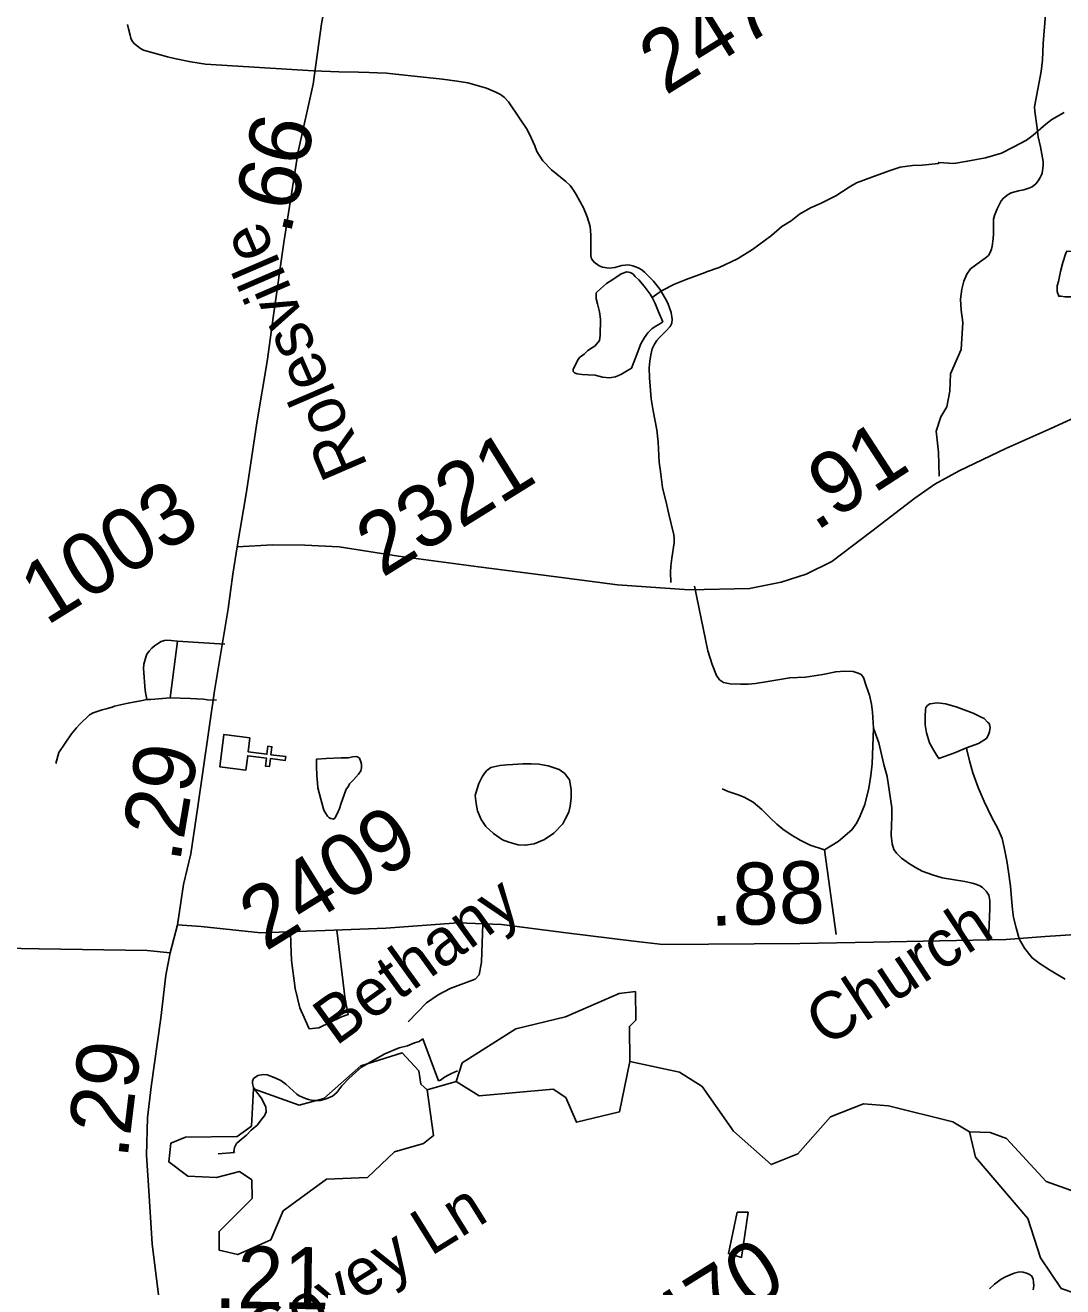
# Model space of a CAD drawing. Extents: x 2001466 to 31450019, y -30647475 to 847247.
# Drawn here: x 2163317 to 2167496, y 761240 to 766322 of the extents above; entities that cross this region are included whole.
import ezdxf

# ---------------------------------------------------------------- set-up
doc = ezdxf.new("R2010")
doc.units = 0
for name, color, linetype in [('Exist Cultural Church CELL', 7, 'Continuous'), ('Exist Hydrographic Misc Water Feature', 7, 'Continuous'), ('Exist Road Non-System Type 51', 7, 'Continuous'), ('Exist Road Secondary Mileage Hundredths English Label', 7, 'Continuous'), ('Exist Road Secondary Type 51 Attributed', 7, 'Continuous'), ('Exist Road Secondary Type 51 Label', 7, 'Continuous'), ('Exist Road Secondary Type 51 Number Label', 7, 'Continuous')]:
    doc.layers.add(name, color=color, linetype=linetype)

msp = doc.modelspace()

# ---------------------------------------------------------------- linework, layer by layer
at = {"layer": 'Exist Cultural Church CELL'}
msp.add_lwpolyline([(2164222.4, 763451.5), (2164215.5, 763395), (2164291, 763385.6), (2164295, 763417.4), (2164310.8, 763415.4), (2164306.9, 763383.6), (2164366.6, 763376.2), (2164364.6, 763360.3), (2164304.9, 763367.7), (2164301, 763336), (2164285.1, 763337.9), (2164289.1, 763369.7), (2164213.5, 763379.1), (2164206.3, 763321.9), (2164100.6, 763335), (2164116.7, 763464.6)], close=True, dxfattribs=at)
at = {"layer": 'Exist Hydrographic Misc Water Feature'}
for p, q in [((2164936.2, 762033.3), (2165053.1, 762066.9)), ((2164094.5, 761776), (2164160.7, 761780.6))]:
    msp.add_line(p, q, dxfattribs=at)
for points in [[(2165842.5, 765225.1), (2165870.6, 765245.2), (2165882.1, 765253.2), (2165932.3, 765279.7), (2165979.9, 765297.6), (2166056.2, 765326.3), (2166061.9, 765328.2), (2166111.8, 765346.6), (2166185.6, 765380.9), (2166247.1, 765419.1), (2166322.8, 765475.8), (2166364.6, 765511.7), (2166402.7, 765534.3), (2166436.4, 765560.5), (2166480.2, 765586.7), (2166520.2, 765604.6), (2166581.7, 765635), (2166635.7, 765669.5), (2166665.8, 765687.6), (2166727.3, 765709.9), (2166797.1, 765736.3), (2166841.1, 765750.3), (2166891, 765756.6), (2166929.3, 765759), (2166995.3, 765765.2), (2166996.8, 765769.4), (2167057.1, 765765.6), (2167112.8, 765774.2), (2167184.8, 765788.4), (2167248.8, 765806.8), (2167297, 765831.1), (2167350.5, 765859.1), (2167376.5, 765879.5), (2167428, 765923.7), (2167451.8, 765942), (2167501.6, 765970.2)], [(2167592.7, 765406.7), (2167663, 765405), (2167658.7, 765393), (2167655.4, 765367.2), (2167651.1, 765347.2), (2167643.5, 765317.1), (2167633.5, 765287), (2167625.9, 765269), (2167613.4, 765253.1), (2167595.7, 765237), (2167556.2, 765230.5), (2167529.7, 765228.4), (2167503.9, 765228.3), (2167489.7, 765230.4), (2167479.9, 765230.2), (2167473.9, 765250.2), (2167473.7, 765272.2), (2167479.7, 765290.3), (2167487.3, 765330.1), (2167497.1, 765366.4), (2167509, 765404.4), (2167512.9, 765412.3), (2167592.7, 765406.7)], [(2165842.5, 765225.1), (2165834.1, 765238.9), (2165810.1, 765271), (2165788.2, 765296.6), (2165773.8, 765310.6), (2165764, 765320.6), (2165754, 765326.5), (2165740, 765328.7), (2165717.7, 765320.2), (2165696.1, 765306), (2165684.2, 765298.1), (2165658.2, 765282.2), (2165634.6, 765259.8), (2165620.7, 765247.7), (2165616.6, 765243.9), (2165616.8, 765219.9), (2165622.9, 765199.9), (2165630.7, 765167.9), (2165635, 765138), (2165633.4, 765071.8), (2165629.7, 765052), (2165611.4, 765029.6), (2165601.6, 765023.8), (2165583.8, 765011.5), (2165568, 764997.7), (2165549.9, 764983.4), (2165541.9, 764971.6), (2165536.2, 764959.5), (2165528.2, 764945.3), (2165524.1, 764935.4), (2165523.9, 764927.3), (2165530.2, 764921.4), (2165540.1, 764917.5), (2165560.2, 764915.7), (2165584.2, 764913.7), (2165612.3, 764911.9), (2165642.4, 764904), (2165670.7, 764902.2), (2165694.3, 764906.4), (2165718.5, 764916.5), (2165759.9, 764940.6), (2165778.1, 764988.6), (2165797.4, 765038.8), (2165811.2, 765064.8), (2165825.3, 765082.9), (2165841.1, 765099.2), (2165855, 765109.2), (2165869.2, 765117.2), (2165885, 765127.4), (2165868.6, 765167.2), (2165854.6, 765201), (2165842.5, 765225.1)], [(2167108.1, 763410.7), (2167064.2, 763392.6), (2167020.4, 763376.1), (2166996.6, 763367.9), (2166988.4, 763380.1), (2166976.3, 763400.2), (2166959.9, 763431.9), (2166948, 763471.9), (2166941.6, 763503.6), (2166941.4, 763537.7), (2166943.7, 763565.8), (2166945.3, 763573.7), (2166951.3, 763581.7), (2166961.3, 763587.9), (2166991.2, 763591.9), (2167023.4, 763588.2), (2167067.3, 763576.3), (2167099.3, 763564.5), (2167135.4, 763551), (2167167.4, 763534.8), (2167179.7, 763528.9), (2167193.4, 763515), (2167199.8, 763509.2), (2167201.6, 763505.3), (2167203.5, 763493.2), (2167201.8, 763475.2), (2167196.1, 763461.1), (2167189.7, 763449), (2167156.3, 763429), (2167108.1, 763410.7)], [(2167108.1, 763410.7), (2167110.2, 763402.7), (2167120.4, 763358.9), (2167134.4, 763311), (2167155.1, 763251.1), (2167179.3, 763195.1), (2167209.4, 763133.3), (2167235.9, 763083.5), (2167252.3, 763045.7), (2167260.7, 763009.6), (2167270.7, 762955.7), (2167277.1, 762911.8), (2167285.3, 762853.7), (2167289.8, 762804), (2167293.9, 762759.9), (2167298, 762728.1), (2167308.2, 762685.9), (2167320.1, 762642.4), (2167342.7, 762604.4), (2167372.6, 762564.7), (2167404.8, 762540.7), (2167443.4, 762516.6), (2167477, 762496.9), (2167505.5, 762479.3)], [(2164655.3, 763375.1), (2164649.1, 763376.9), (2164635.2, 763374.9), (2164619.2, 763370.8), (2164589.5, 763370.5), (2164529.2, 763368.2), (2164491.2, 763365.8), (2164491.2, 763337.9), (2164491.4, 763298.1), (2164494.1, 763270.1), (2164495.8, 763249.9), (2164508.3, 763204.3), (2164520.4, 763160.2), (2164528.4, 763146.1), (2164534.7, 763136.2), (2164540.5, 763130.4), (2164548.9, 763126.3), (2164558.7, 763124.4), (2164564.9, 763128.3), (2164574.5, 763148.4), (2164582.7, 763166.6), (2164590.1, 763188.6), (2164602.2, 763222.5), (2164610.2, 763244.8), (2164618.2, 763254.6), (2164623.9, 763266.7), (2164639.9, 763282.9), (2164659.8, 763305.1), (2164669.2, 763319), (2164671.7, 763330.8), (2164671.5, 763345.1), (2164669.2, 763355.1), (2164663.1, 763369.1), (2164655.3, 763375.1)], [(2165321.1, 763346.6), (2165281.3, 763344.6), (2165257.1, 763342.1), (2165229, 763340.3), (2165193.3, 763331.9), (2165177.1, 763319.7), (2165169.1, 763310), (2165157.7, 763293.9), (2165143.9, 763267.6), (2165135.7, 763241.6), (2165130, 763219.7), (2165133.9, 763187.5), (2165138.4, 763157.7), (2165154.4, 763121.9), (2165172.8, 763094), (2165203, 763066), (2165239.1, 763040.2), (2165265.1, 763030.6), (2165303, 763020.8), (2165331.1, 763018.6), (2165367, 763024.9), (2165408.8, 763041.3), (2165446.8, 763067.6), (2165482.5, 763105.6), (2165492.5, 763123.6), (2165506.2, 763151.9), (2165512.4, 763175.8), (2165515.9, 763209.7), (2165515.7, 763243.8), (2165509.1, 763281.7), (2165491.3, 763307.5), (2165467.3, 763323.3), (2165423.2, 763339.3), (2165385.5, 763345), (2165355.1, 763346.8), (2165321.1, 763346.6)], [(2165053.1, 762066.9), (2165077.1, 762141.9), (2165293.2, 762278.6), (2165493.1, 762327), (2165709.3, 762420.9), (2165775.1, 762429.4), (2165776.1, 762314.6), (2165751.1, 762288.9), (2165752.1, 762147.8)], [(2164160.7, 761780.6), (2164158.2, 761784.6), (2164160.1, 761800.6), (2164168.3, 761816.8), (2164188, 761834.5), (2164208.1, 761850.9), (2164228, 761871.1), (2164251.7, 761891), (2164273.5, 761919.4), (2164281.5, 761929.1), (2164287.4, 761945.2), (2164287, 761963.1), (2164279, 761981.4), (2164267.1, 762001), (2164244.8, 762031.2), (2164237, 762042.9), (2164232.5, 762059), (2164232.9, 762068.7), (2164236.8, 762079), (2164254.4, 762091), (2164276.3, 762095), (2164292.1, 762093.3), (2164320.6, 762083.4), (2164346.9, 762071.7), (2164366.6, 762055.7), (2164411.1, 762015.8), (2164421.1, 762009.8), (2164446.7, 761998.2), (2164458.8, 761994.4), (2164470.7, 761992.1), (2164484.9, 761990.4), (2164505, 761990.6), (2164529, 761996.7), (2164555.2, 762008.6), (2164572.9, 762023), (2164592.9, 762049.1), (2164620.4, 762079), (2164648.5, 762105.2), (2164671.9, 762125.2), (2164706.3, 762145.5), (2164766, 762177.9), (2164823.6, 762202), (2164857.7, 762210.3), (2164885.8, 762222.7), (2164903.8, 762228.5), (2164919.4, 762238.7), (2164982.1, 762069.4)], [(2164936.2, 762033.3), (2164962.2, 761849), (2164921.2, 761817.1), (2164804.2, 761783.4), (2164696.1, 761680.6), (2164530.2, 761674.2), (2164356.1, 761546.6), (2164306.1, 761429.5), (2164173.2, 761369.9), (2164098.2, 761387.8), (2164098.2, 761463.3), (2164231.2, 761595.1), (2164230.2, 761670.5), (2164180.2, 761704.4), (2164088.1, 761680), (2163972.3, 761685.7), (2163896.2, 761743), (2163904.2, 761818.3), (2163963.2, 761843.3), (2164171.2, 761845.6), (2164229.2, 761887.1), (2164236.2, 762037.8), (2164420.1, 761971.7), (2164520.2, 761999.2), (2164669.2, 762130.7), (2164835.1, 762183), (2164902.2, 762109.4), (2164911.2, 762056.8), (2164936.2, 762033.3)], [(2165494.1, 762002.1), (2165537.2, 761902.8), (2165711.1, 761945.2), (2165752.1, 762147.8)], [(2167120.2, 761863.8), (2167053.2, 761904.5), (2166794.2, 761968.9), (2166694.1, 761977.5), (2166561.2, 761924.5), (2166429.2, 761776.3), (2166321.1, 761732.6), (2166170.2, 761866.9), (2166044.1, 762046.7), (2165952.2, 762104.3), (2165752.1, 762147.8)], [(2165058.2, 762109.4), (2165034.2, 762099.2), (2165024, 762093.4), (2165006.5, 762085.1), (2164990.3, 762073), (2164982.1, 762069.4)], [(2165053.1, 762066.9), (2165145.2, 762009.3), (2165444.1, 762036), (2165494.1, 762002.1)], [(2167406.1, 761356.1), (2167355.2, 761514.6), (2167145.2, 761761.6), (2167120.2, 761863.8)], [(2167814.1, 761282.1), (2167781.1, 761364.7), (2167780.1, 761466.4), (2167546.1, 761622.2), (2167429.2, 761664), (2167270.1, 761837.8), (2167203.3, 761862.1), (2167120.2, 761863.8)], [(2166185.2, 761540.2), (2166149.7, 761374), (2166202, 761358.3), (2166228.9, 761540.1), (2166185.2, 761540.2)], [(2167814.1, 761282.1), (2167782.1, 761167.9), (2167682.1, 761166.7), (2167490.1, 761232.9), (2167406.1, 761356.1)]]:
    msp.add_lwpolyline(points, dxfattribs=at)
at = {"layer": 'Exist Road Non-System Type 51'}
for p, q in [((2163901.4, 763612.8), (2163931.1, 763841.2)), ((2164121.2, 763829.1), (2163931.1, 763841.2)), ((2166584.1, 762658.9), (2166536.5, 763000.5))]:
    msp.add_line(p, q, dxfattribs=at)
for points in [[(2167452.9, 766700.5), (2167417.8, 766248), (2167414.3, 766182.1), (2167408.7, 766136.2), (2167381.8, 765993.4), (2167384, 765974.8), (2167393.2, 765908), (2167397.5, 765872.1), (2167406.1, 765832.1), (2167417.1, 765773.9), (2167417.4, 765758.5), (2167416.3, 765746.1), (2167415.1, 765736.2), (2167412.9, 765726.6), (2167410.2, 765718.9), (2167405.4, 765709.4), (2167397.3, 765695.9), (2167387.7, 765683.9), (2167373.6, 765671.8), (2167359.7, 765665.7), (2167339.8, 765659.5), (2167317.9, 765655.2), (2167287.9, 765647), (2167276.4, 765639.8), (2167258.1, 765625), (2167248.2, 765614.6), (2167232.6, 765582.3), (2167220.8, 765556.2), (2167217.6, 765541.6), (2167217.2, 765524.2), (2167217.7, 765482.2), (2167216.3, 765461.7), (2167212.1, 765432.2), (2167209.7, 765420), (2167204.4, 765406.1), (2167196.7, 765394.7), (2167184.3, 765383.5), (2167164.6, 765370.5), (2167125, 765341.1), (2167109.4, 765319.1), (2167097.6, 765290.9), (2167090, 765258.9), (2167084.3, 765218.8), (2167086.8, 765174.7), (2167093.4, 765124.8), (2167086.6, 765015.3), (2167044.1, 764918.1), (2167041, 764848.2), (2167028.9, 764784.5), (2167004.6, 764745), (2166986.4, 764687.3), (2166995.5, 764602.2), (2166998.5, 764505.1)], [(2164479, 766138.9), (2164043.8, 766166), (2163985, 766174.2), (2163918.9, 766187.6), (2163890.8, 766195.4), (2163818.6, 766214.6), (2163794.4, 766222.3), (2163781.5, 766229), (2163757.3, 766247.9), (2163748.1, 766257.9), (2163742.4, 766270.8), (2163739.8, 766281.6), (2163733.5, 766307.6), (2163729.3, 766325.6)], [(2164479, 766138.9), (2164580.1, 766134.4), (2164660, 766133.2), (2164702.2, 766131.7), (2164736.2, 766130), (2164772.1, 766128.5), (2164858.3, 766119.3), (2164998.4, 766104.9), (2165056.7, 766097.5), (2165100.7, 766090), (2165174.8, 766068.6), (2165213.1, 766053.1), (2165232.1, 766043.5), (2165247.3, 766031.4), (2165263.5, 766013), (2165308.2, 765948.1), (2165338.6, 765902.3), (2165357.1, 765866.5), (2165369.5, 765836.7), (2165377.6, 765812.9), (2165386.7, 765798.7), (2165402.6, 765776.2), (2165436.5, 765739.5), (2165494.9, 765692.1), (2165511.8, 765677), (2165525.4, 765658.3), (2165536, 765640.5), (2165566.1, 765586.9), (2165580.6, 765551), (2165592.9, 765511.1), (2165595.3, 765477.1), (2165596, 765415.1), (2165596.1, 765393.1), (2165598.3, 765381.2), (2165608.4, 765367.2), (2165628.5, 765353.4), (2165642.8, 765348.1), (2165669.5, 765343.6), (2165692.2, 765346.3), (2165720.5, 765354.5), (2165746.6, 765356.8), (2165764.5, 765353.2), (2165786.7, 765345.2), (2165800.2, 765337.5), (2165811, 765327.5), (2165847.2, 765291.7), (2165873.1, 765258.6), (2165896.1, 765220.3), (2165905.8, 765202.2), (2165918.6, 765164.5), (2165922.9, 765138.6), (2165921.1, 765122.6), (2165915.2, 765108.6), (2165897.5, 765090.3), (2165881.5, 765074.3), (2165871.7, 765064.1), (2165861.9, 765051.9), (2165852, 765037.9), (2165843, 765018.1), (2165836.5, 764993.8), (2165832.6, 764968.9), (2165831, 764941.7), (2165831.4, 764901.7), (2165838.3, 764817.8), (2165847.1, 764768.4), (2165861.7, 764691.9), (2165866.1, 764642), (2165871, 764562.1), (2165875.5, 764524.2), (2165879.8, 764492.2), (2165884.1, 764460.3), (2165900.9, 764388.3), (2165909.3, 764352.6), (2165930.2, 764268.8), (2165930.9, 764254.7), (2165930.6, 764236.8), (2165921.1, 764174.8), (2165917.4, 764142.6), (2165915.7, 764118.7), (2165917.3, 764076.6)], [(2166733.3, 763490.6), (2166729.9, 763555.2), (2166725.5, 763587.1), (2166717.2, 763623.1), (2166704.8, 763660.9), (2166693.9, 763694.2), (2166684.2, 763706.8), (2166672.3, 763712.6), (2166652.2, 763718.4), (2166619.1, 763720.5), (2166582.2, 763717.7), (2166530.2, 763707.1), (2166460.4, 763696.3), (2166396.3, 763693.7), (2166308.4, 763678.9), (2166258.5, 763670.3), (2166228.6, 763667.9), (2166198.6, 763667.5), (2166156.5, 763669.2), (2166130.4, 763674.9), (2166113.6, 763685.7), (2166102.2, 763702.7), (2166083.7, 763746.5), (2166067, 763802.2), (2166013.2, 764063.1)], [(2163931.1, 763841.2), (2163904.6, 763843.5), (2163888.4, 763845.3), (2163878.6, 763843.3), (2163864.5, 763839), (2163850.7, 763830.8), (2163838.7, 763822.7), (2163826.7, 763812.7), (2163816.9, 763800.5), (2163807, 763788.3), (2163803.2, 763776.4), (2163795.4, 763748.4), (2163793.6, 763730.2), (2163800.6, 763642.3), (2163807.5, 763605.9)], [(2163807.5, 763605.9), (2163783, 763600.2), (2163767.1, 763598), (2163725.2, 763589.6), (2163677.2, 763579), (2163667.3, 763575), (2163643.4, 763568.7), (2163627.5, 763564.4), (2163591.4, 763552.2), (2163575.7, 763543.9), (2163536.1, 763505.5), (2163524.2, 763491.4), (2163504.3, 763467.2), (2163453.2, 763392.6), (2163440.3, 763348.1)], [(2163807.5, 763605.9), (2163822.9, 763606.6), (2163901.4, 763612.8)], [(2163901.4, 763612.8), (2163983, 763610.3), (2164009.1, 763608.6), (2164035.1, 763606.9), (2164051, 763605), (2164087.6, 763602.8)], [(2166536.5, 763000.5), (2166591.4, 763033.7), (2166646.9, 763080.4), (2166666.5, 763108.6), (2166680.3, 763136.7), (2166699, 763183.5), (2166715.2, 763249.2), (2166723.6, 763299.8), (2166728, 763347.3), (2166733.3, 763490.6)], [(2166733.3, 763490.6), (2166755.1, 763431.5), (2166776.1, 763343.7), (2166788.7, 763295.9), (2166807.9, 763170.1), (2166808.4, 763134.1), (2166805.1, 763060), (2166809.5, 763024.1), (2166815.7, 763002.1), (2166826, 762986.3), (2166846.2, 762966.5), (2166874.3, 762946.7), (2166902.6, 762929.2), (2166930.1, 762914.8), (2166971, 762899.8), (2167010.7, 762888), (2167052.4, 762880.7), (2167101.2, 762873.1), (2167131.2, 762865.5), (2167146, 762861.6), (2167161.6, 762855.7), (2167172.9, 762848.4), (2167187.6, 762834.1), (2167198.8, 762817.5), (2167202, 762796.2), (2167202.3, 762762.2), (2167198.2, 762667.5)], [(2166123.8, 763246.1), (2166149.2, 763235.2), (2166189.3, 763221.6), (2166213.3, 763211.9), (2166249.7, 763192.1), (2166283.9, 763162.6), (2166318.4, 763128.9), (2166344.6, 763103.2), (2166368.8, 763083.5), (2166402.5, 763060.2), (2166438.7, 763039.3), (2166479.5, 763018.6), (2166536.5, 763000.5)], [(2165160.1, 762702.7), (2165155.6, 762547.2), (2165145.7, 762496.1), (2165129.2, 762479.6), (2165029.4, 762441.4), (2164980.7, 762415.8), (2164934.2, 762383.3), (2164860.3, 762307.9)], [(2164572.4, 762676.8), (2164606.2, 762397), (2164618.4, 762337.3), (2164591.7, 762328), (2164500, 762283.8), (2164461.6, 762279.2), (2164446.1, 762312.9), (2164423, 762364), (2164404.9, 762441.6), (2164389.6, 762554.6), (2164386.8, 762621.5), (2164385.2, 762670.3)], [(2167376.8, 761227.8), (2167379.5, 761243.2), (2167378.6, 761258), (2167376.7, 761271.4), (2167370.3, 761283.8), (2167362.9, 761289.5), (2167354.2, 761293.7), (2167336.1, 761299.5), (2167325.7, 761300.3), (2167316.1, 761299.3), (2167300.4, 761294.8), (2167284.7, 761288.5), (2167265.3, 761279.5), (2167248.3, 761270.5), (2167220.7, 761250.2), (2167200.7, 761232)]]:
    msp.add_lwpolyline(points, dxfattribs=at)
at = {"layer": 'Exist Road Secondary Type 51 Attributed'}
for points in [[(2164731.1, 767701.7), (2164658, 767289.5), (2164592.6, 766856), (2164571.7, 766728.2), (2164537.2, 766472.7), (2164510.5, 766328.2), (2164477, 766084.3), (2164416.8, 765814.1), (2164358.8, 765446.6), (2164316.9, 765154.4), (2164291.3, 764967), (2164249.9, 764720.9), (2164208.1, 764442.4), (2164171.5, 764221.4)], [(2164171.5, 764221.4), (2164315.3, 764228.7), (2164444.1, 764227.7), (2164582.2, 764220.4), (2164820.7, 764182.7), (2165143.6, 764140.8), (2165446, 764101), (2165702.9, 764067.5), (2165991.7, 764047.6), (2166234.9, 764052.8), (2166362.6, 764079), (2166463, 764111.5), (2166565.6, 764161.7), (2166727.3, 764284.2), (2166901, 764417.2), (2166981.5, 764473.8), (2167078.3, 764527.2), (2167266.7, 764617.2), (2167448.7, 764697.9), (2167683.7, 764804.7)], [(2164171.5, 764221.4), (2164153.7, 764110.4), (2164134.3, 763971.2), (2164079.4, 763640.3), (2164010.9, 763165.9), (2163984.7, 762984.8), (2163955.4, 762861.2), (2163930.3, 762697.9)], [(2157917.2, 763772.2), (2157942.3, 763738.7), (2157989.4, 763656), (2158099.8, 763453.9), (2158258.9, 763183.7), (2158334.2, 763068.5), (2158430.5, 762968), (2158522.6, 762894.7), (2158655.5, 762827.7), (2158789.4, 762779.5), (2158912.9, 762754.4), (2159289.6, 762748.1), (2160263.7, 762706.2), (2160768.1, 762685.3), (2161673.2, 762645.5), (2162311.5, 762624.6), (2163007.4, 762607.8), (2163373.6, 762601.5), (2163808.9, 762595.2), (2163901.5, 762585.8)], [(2163930.3, 762697.9), (2163901.5, 762585.8)], [(2163930.3, 762697.9), (2164025.5, 762691.6), (2164266.2, 762666.4), (2164525.1, 762674.8), (2164770, 762685.3), (2165061.4, 762706.2), (2165235.1, 762699.9), (2165496.7, 762666.4), (2165768.8, 762632.9), (2165886, 762618.3), (2166437.4, 762622.5), (2166734.6, 762628.7), (2167268.2, 762639.2), (2167425.2, 762651.8), (2167568.5, 762660.2), (2167861.5, 762643.4), (2168311.5, 762595.2), (2168563.7, 762581.6)], [(2163901.5, 762585.8), (2163884.2, 762495.8), (2163863.3, 762321.9), (2163824.1, 762045.5), (2163810.5, 761920.9), (2163806.3, 761770.1), (2163816.2, 761606.7), (2163828.8, 761412), (2163866, 761112.8)]]:
    msp.add_lwpolyline(points, dxfattribs=at)

# ---------------------------------------------------------------- texts
at = {"layer": 'Exist Road Secondary Mileage Hundredths English Label'}
for s, rotation, p in [('.66', 77.4447, (2164384.7, 765472.9)), ('.91', 33.0357, (2166501, 764280.9)), ('.29', 80.466, (2163939.6, 762945)), ('.88', 1.5278, (2166075.7, 762694.1)), ('.29', 83.1033, (2163728.8, 761751.9)), ('.21', 359.2349, (2164076.9, 761154.8))]:
    msp.add_text(s, height=250, rotation=rotation, dxfattribs=at).set_placement(p)
at = {"layer": 'Exist Road Secondary Type 51 Label'}
for s, rotation, p in [('Rolesville', 113.3398, (2164699.6, 764546.2)), ('Bethany', 35.8381, (2164568.6, 762207.6)), ('Church', 33.3875, (2166544, 762203.2)), ('Quail Covey Ln', 31.918, (2163716.3, 760592.3))]:
    msp.add_text(s, height=190, rotation=rotation, dxfattribs=at).set_placement(p)
at = {"layer": 'Exist Road Secondary Type 51 Number Label'}
for s, p in [('2477', (2165895.8, 766037.4)), ('2321', (2164755.5, 764094.6)), ('1003', (2163402.8, 763900.9)), ('2409', (2164285.1, 762589.1)), ('2470', (2165764.4, 760844.7))]:
    msp.add_text(s, height=250, rotation=31.918, dxfattribs=at).set_placement(p)

doc.saveas('drawing.dxf')
